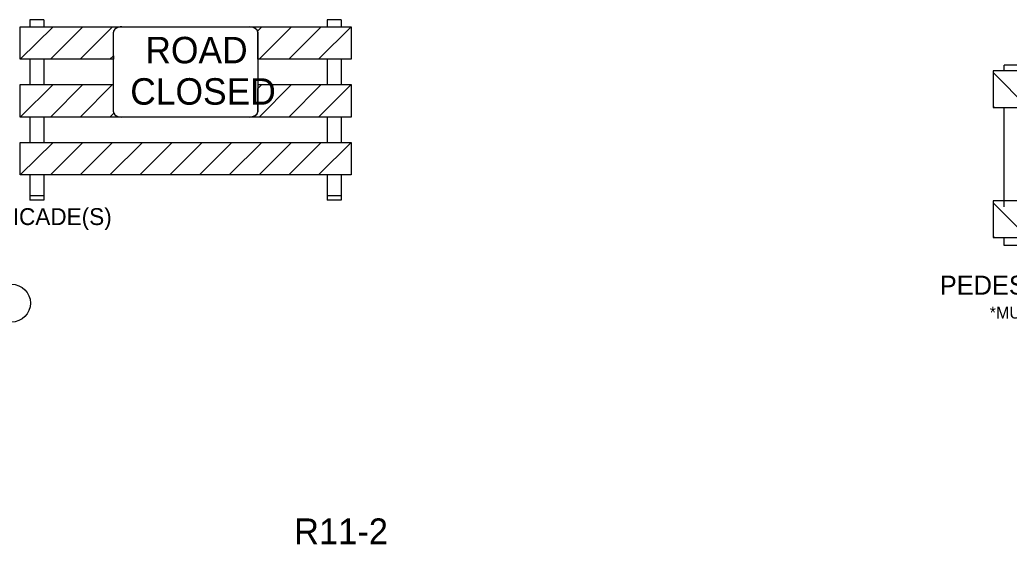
# Model space of a CAD drawing. Extents: x 2157572 to 5059327, y 715220 to 1674494.
# Drawn here: x 2161225 to 2163528, y 718993 to 720213 of the extents above; entities that cross this region are included whole.
import ezdxf

# ---------------------------------------------------------------- set-up
doc = ezdxf.new("R2010")
doc.units = 0
for name, color, linetype in [('Exist Cultural Church Label', 7, 'Continuous'), ('Exist Hydrographic Creek Single Shore Label', 7, 'Continuous'), ('Exist Road Secondary Structure Culvert Number Label', 7, 'Continuous'), ('Map Preparation County Base Legend Hangar on Field', 7, 'Continuous'), ('Map Preparation County Base Legend Highway Garage or Maintenance Office', 7, 'Continuous'), ('Map Preparation County Base Legend Marked Auxillary Field', 7, 'Continuous')]:
    doc.layers.add(name, color=color, linetype=linetype)

# ---------------------------------------------------------------- blocks, each defined once
blk = doc.blocks.new('PEDBARRSWCLOSED')
at = {"layer": 'Map Preparation County Base Legend Hangar on Field'}
for p, q in [((26.5, 0), (0, 0)), ((0, 0), (-26.5, 0))]:
    blk.add_line(p, q, dxfattribs=at)
for points in [[(-26.5, 30), (0, 30)], [(0, 30), (26.5, 30)], [(-30, 1.75), (-30, 28.25)], [(30, 28.25), (30, 1.75)]]:
    blk.add_lwpolyline(points, dxfattribs=at)
for centre, major_axis, start_param, end_param in [((-26.5, 28.25), (-3.5, 0), 4.712162, 6.283185), ((26.5, 28.25), (3.5, 0), 0, 1.570796), ((-26.5, 1.75), (-3.5, 0), 0, 1.570796), ((26.5, 1.75), (-3.5, 0), 1.570796, 3.141593)]:
    blk.add_ellipse(centre, major_axis=major_axis, ratio=0.5, start_param=start_param, end_param=end_param, dxfattribs=at)
at = {"layer": 'Map Preparation County Base Legend Marked Auxillary Field'}
for p, q in [((-37.19, 30), (-43.76, 30)), ((-43.76, 27.64), (-43.76, 30)), ((-37.19, 27.64), (-37.19, 30)), ((43.76, 30), (37.19, 30)), ((37.19, 27.64), (37.19, 30)), ((43.76, 27.64), (43.76, 30.06)), ((-48.36, 27.64), (-48.36, 12.46)), ((-30, 27.64), (-48.36, 27.64)), ((-35.14, 27.64), (-48.36, 27.64)), ((-30, 22.5), (-35.14, 27.64)), ((30, 21.58), (36.06, 27.64)), ((48.36, 27.64), (30, 27.64)), ((36.06, 27.64), (48.36, 27.64)), ((48.36, 12.46), (48.36, 27.64)), ((-47.82, 12.46), (-48.36, 13.01)), ((-48.36, 12.46), (-47.82, 12.46)), ((-48.36, 12.46), (-30, 12.46)), ((-43.76, -14.53), (-43.76, 12.46)), ((-37.19, -14.53), (-37.19, 12.46)), ((30, 12.46), (48.36, 12.46)), ((37.19, -14.53), (37.19, 12.46)), ((43.76, -14.53), (43.76, 12.46)), ((-43.76, -28.8), (-43.76, -14.53)), ((-37.19, -28.7), (-37.19, -14.53)), ((37.19, -33.18), (37.19, -14.53)), ((43.76, -32.25), (43.76, -14.53)), ((-48.36, -26.35), (-48.36, -41.53)), ((48.36, -26.35), (-48.36, -26.35)), ((-35.14, -26.35), (-48.36, -26.35)), ((-19.97, -41.53), (-35.14, -26.35)), ((-6.04, -41.53), (-21.21, -26.35)), ((-21.21, -26.35), (-7.29, -26.35)), ((-7.29, -26.35), (0.46, -34.1)), ((0.46, -34.1), (8.21, -26.35)), ((22.13, -26.35), (6.96, -41.53)), ((8.21, -26.35), (22.13, -26.35)), ((20.89, -41.53), (36.06, -26.35)), ((36.06, -26.35), (48.36, -26.35)), ((48.36, -41.53), (48.36, -26.35)), ((65.44, -34.49), (65.44, -41.53)), ((-47.82, -41.53), (-48.36, -40.98)), ((-48.36, -41.53), (-47.82, -41.53)), ((-48.36, -41.53), (48.36, -41.53)), ((-43.76, -44.81), (-43.76, -41.53)), ((-37.19, -44.81), (-43.76, -44.81)), ((-37.19, -44.81), (-37.19, -41.53)), ((-33.89, -41.53), (-19.97, -41.53)), ((6.96, -41.53), (-6.96, -41.53)), ((34.81, -41.53), (20.89, -41.53)), ((37.19, -44.81), (37.19, -41.53)), ((43.76, -44.81), (37.19, -44.81)), ((43.76, -44.81), (43.76, -41.53)), ((51.11, -44.81), (66.83, -44.81)), ((53.37, -41.53), (66.83, -41.53)), ((65.44, -44.81), (65.44, -51.17))]:
    blk.add_line(p, q, dxfattribs=at)
for points in [[(-48.36, 27.64), (-48.36, 26.93), (-33.89, 12.46)], [(48.36, 27.64), (48.36, 26.01), (34.81, 12.46)], [(-33.89, 12.46), (-30, 12.46), (-30, 22.5)], [(34.81, 12.46), (30, 12.46), (30, 21.58)], [(-48.36, -26.35), (-48.36, -27.06), (-33.89, -41.53)], [(48.36, -26.35), (48.36, -27.98), (34.81, -41.53)]]:
    blk.add_lwpolyline(points, dxfattribs=at)
at = {"layer": 'Map Preparation County Base Legend Hangar on Field'}
for s, p in [('SIDEWALK', (-26.54, 17.9)), ('CLOSED', (-21.11, 4.07))]:
    blk.add_text(s, height=8.172, dxfattribs=at).set_placement(p)
at = {"layer": 'Map Preparation County Base Legend Marked Auxillary Field'}
for s, height, p in [('2" MAX', 6, (70.36, -45.51)), ('PEDESTRIAN BARRICADE', 7.8816, (-70.5, -65.23)), ('*MUST BE ADA-COMPLIANT*', 5, (-49.77, -75.16))]:
    blk.add_text(s, height=height, dxfattribs=at).set_placement(p)

msp = doc.modelspace()

# ---------------------------------------------------------------- linework, layer by layer
at = {"layer": 'Exist Cultural Church Label'}
msp.add_circle((2161206, 719553.4), 44.1, dxfattribs=at)
at = {"layer": 'Exist Road Secondary Structure Culvert Number Label'}
for p, q in [((2161281.5, 720212.7), (2161248.8, 720212.7)), ((2161248.8, 720212.7), (2161248.8, 720196.3)), ((2161281.5, 720212.7), (2161281.5, 720196.3)), ((2161973.6, 720212.7), (2161940.9, 720212.7)), ((2161940.9, 720212.7), (2161940.9, 720196.3)), ((2161973.6, 720212.7), (2161973.6, 720196.3)), ((2161225.9, 720196.3), (2161996.5, 720196.3)), ((2161225.9, 720120.8), (2161225.9, 720196.3)), ((2161225.9, 720120.8), (2161225.9, 720196.3)), ((2161225.9, 720196.3), (2161302.7, 720196.3)), ((2161302.7, 720196.3), (2161225.9, 720120.8)), ((2161296.5, 720120.8), (2161372.1, 720196.3)), ((2161441.4, 720196.3), (2161365.9, 720120.8)), ((2161372.1, 720196.3), (2161441.4, 720196.3)), ((2161778.7, 720186.6), (2161788.5, 720196.3)), ((2161857.8, 720196.3), (2161782.2, 720120.8)), ((2161788.5, 720196.3), (2161857.8, 720196.3)), ((2161851.6, 720120.8), (2161927.1, 720196.3)), ((2161996.5, 720196.3), (2161920.9, 720120.8)), ((2161927.1, 720196.3), (2161996.5, 720196.3)), ((2161996.5, 720196.3), (2161996.5, 720120.8)), ((2161779.2, 720120.8), (2161779.2, 720184.1)), ((2161443.2, 720120.8), (2161225.9, 720120.8)), ((2161248.8, 720120.8), (2161248.8, 720061.9)), ((2161281.5, 720120.8), (2161281.5, 720061.9)), ((2161365.9, 720120.8), (2161296.5, 720120.8)), ((2161435.2, 720120.8), (2161443.2, 720128.7)), ((2161443.2, 720120.8), (2161435.2, 720120.8)), ((2161443.2, 720128.7), (2161443.2, 720120.8)), ((2161782.2, 720120.8), (2161779.2, 720120.8)), ((2161996.5, 720120.8), (2161779.2, 720120.8)), ((2161920.9, 720120.8), (2161851.6, 720120.8)), ((2161940.9, 720120.8), (2161940.9, 720061.9)), ((2161973.6, 720120.8), (2161973.6, 720061.9)), ((2161225.9, 719986.3), (2161225.9, 720061.9)), ((2161225.9, 719986.3), (2161225.9, 720061.9)), ((2161225.9, 720061.9), (2161302.7, 720061.9)), ((2161302.7, 720061.9), (2161225.9, 719986.3)), ((2161225.9, 720061.9), (2161443.2, 720061.9)), ((2161296.5, 719986.3), (2161372.1, 720061.9)), ((2161441.4, 720061.9), (2161365.9, 719986.3)), ((2161372.1, 720061.9), (2161441.4, 720061.9)), ((2161779.2, 720052.6), (2161788.5, 720061.9)), ((2161779.2, 720061.9), (2161996.5, 720061.9)), ((2161779.2, 719998.6), (2161779.2, 720052.6)), ((2161857.8, 720061.9), (2161782.2, 719986.3)), ((2161788.5, 720061.9), (2161857.8, 720061.9)), ((2161851.6, 719986.3), (2161927.1, 720061.9)), ((2161996.5, 720061.9), (2161920.9, 719986.3)), ((2161927.1, 720061.9), (2161996.5, 720061.9)), ((2161996.5, 720061.9), (2161996.5, 719986.3)), ((2161996.5, 719986.3), (2161225.9, 719986.3)), ((2161248.8, 719986.3), (2161248.8, 719927.5)), ((2161281.5, 719986.3), (2161281.5, 719927.5)), ((2161365.9, 719986.3), (2161296.5, 719986.3)), ((2161435.2, 719986.3), (2161444, 719995.1)), ((2161462.8, 719986.3), (2161435.2, 719986.3)), ((2161759.6, 719986.3), (2161462.8, 719986.3)), ((2161782.2, 719986.3), (2161759.7, 719986.3)), ((2161920.9, 719986.3), (2161851.6, 719986.3)), ((2161940.9, 719986.3), (2161940.9, 719927.5)), ((2161973.6, 719986.3), (2161973.6, 719927.5)), ((2161225.9, 719851.9), (2161225.9, 719927.5)), ((2161225.9, 719927.5), (2161302.7, 719927.5)), ((2161302.7, 719927.5), (2161225.9, 719851.9)), ((2161225.9, 719927.5), (2161996.5, 719927.5)), ((2161225.9, 719851.9), (2161225.9, 719927.5)), ((2161296.5, 719851.9), (2161372.1, 719927.5)), ((2161441.4, 719927.5), (2161365.9, 719851.9)), ((2161372.1, 719927.5), (2161441.4, 719927.5)), ((2161435.2, 719851.9), (2161510.8, 719927.5)), ((2161580.1, 719927.5), (2161504.5, 719851.9)), ((2161510.8, 719927.5), (2161580.1, 719927.5)), ((2161574.2, 719851.9), (2161649.8, 719927.5)), ((2161719.1, 719927.5), (2161643.6, 719851.9)), ((2161649.8, 719927.5), (2161719.1, 719927.5)), ((2161712.9, 719851.9), (2161788.5, 719927.5)), ((2161857.8, 719927.5), (2161782.2, 719851.9)), ((2161788.5, 719927.5), (2161857.8, 719927.5)), ((2161851.6, 719851.9), (2161927.1, 719927.5)), ((2161996.5, 719927.5), (2161920.9, 719851.9)), ((2161927.1, 719927.5), (2161996.5, 719927.5)), ((2161996.5, 719927.5), (2161996.5, 719851.9)), ((2161996.5, 719851.9), (2161225.9, 719851.9)), ((2161248.8, 719851.9), (2161248.8, 719793)), ((2161281.5, 719851.9), (2161281.5, 719793)), ((2161365.9, 719851.9), (2161296.5, 719851.9)), ((2161504.5, 719851.9), (2161435.2, 719851.9)), ((2161643.6, 719851.9), (2161574.2, 719851.9)), ((2161782.2, 719851.9), (2161712.9, 719851.9)), ((2161920.9, 719851.9), (2161851.6, 719851.9)), ((2161940.9, 719851.9), (2161940.9, 719793)), ((2161973.6, 719851.9), (2161973.6, 719793)), ((2161281.5, 719802.8), (2161248.8, 719802.8)), ((2161973.6, 719802.8), (2161940.9, 719802.8)), ((2161281.5, 719793), (2161248.8, 719793)), ((2161973.6, 719793), (2161940.9, 719793))]:
    msp.add_line(p, q, dxfattribs=at)
for points in [[(2161462.8, 720196.3), (2161759.6, 720196.3)], [(2161443.2, 719998.6), (2161443.2, 720184.1)], [(2161779.2, 720184.1), (2161779.2, 719998.6)]]:
    msp.add_lwpolyline(points, dxfattribs=at)
for centre, major_axis, start_param, end_param in [((2161462.8, 720184.1), (-19.6, 0), 4.712162, 6.283185), ((2161759.6, 720184.1), (19.6, 0), 0, 1.570796), ((2161759.6, 720184.1), (19.6, 0), 6.283185, 6.491582), ((2161462.8, 719998.6), (-19.6, 0), 0, 1.571024), ((2161462.8, 719998.6), (-19.6, 0), 0.287132, 1.570688), ((2161759.6, 719998.6), (-19.6, 0), 1.570796, 3.141593), ((2161759.6, 719998.6), (19.6, 0), 4.712389, 6.283185)]:
    msp.add_ellipse(centre, major_axis=major_axis, ratio=0.625, start_param=start_param, end_param=end_param, dxfattribs=at)
at = {"layer": 'Map Preparation County Base Legend Highway Garage or Maintenance Office'}
msp.add_circle((2161206, 719553.4), 44.1, dxfattribs=at)

# ---------------------------------------------------------------- block references
at = {"layer": 'Exist Hydrographic Creek Single Shore Label', "xscale": 5.605313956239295, "yscale": 5.605313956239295}
msp.add_blockref('PEDBARRSWCLOSED', (2163761.8, 719938.8), dxfattribs=at)

# ---------------------------------------------------------------- texts
at = {"layer": 'Exist Road Secondary Structure Culvert Number Label'}
for s, height, p in [('ROAD', 61.6, (2161517.6, 720111.4)), ('CLOSED', 61.6, (2161482.4, 720015.2)), ('TYPE III BARRICADE(S)', 39.25, (2160853.1, 719735.1))]:
    msp.add_text(s, height=height, dxfattribs=at).set_placement(p)
msp.add_text('R11-2', height=60, rotation=360, dxfattribs=at).set_placement((2161863.7, 718992.5))

doc.saveas('drawing.dxf')
